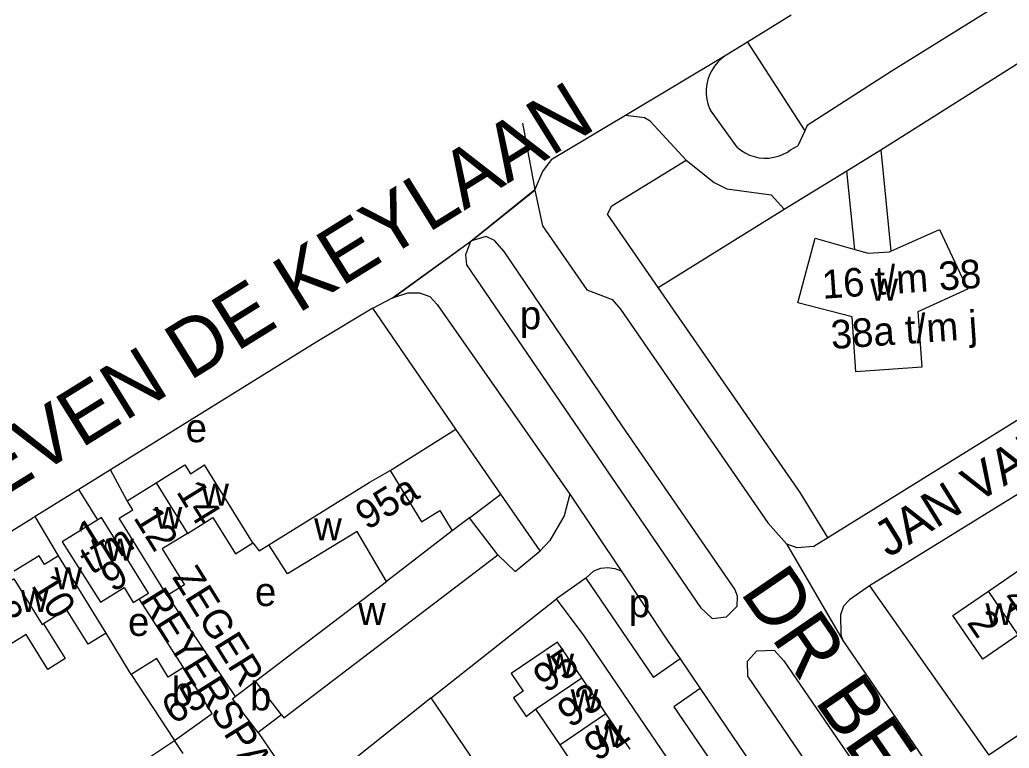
# Model space of a CAD drawing. Extents: x 159294 to 161936, y 384538 to 386517.
# Drawn here: x 159966.9 to 160105.1, y 386032 to 386133.9 of the extents above; entities that cross this region are included whole.
import ezdxf

# ---------------------------------------------------------------- set-up
doc = ezdxf.new("R2010")
doc.units = 0
for name, color, linetype in [('BLT_Basislijn', 7, 'Continuous'), ('BLT_Bebouwing', 7, 'Continuous'), ('BLT_Centroide', 7, 'Continuous'), ('BLT_Huisnummer', 7, 'Continuous'), ('BLT_Huisnummer_ tussenligend', 7, 'Continuous'), ('BLT_Huisnummer_reeks', 7, 'Continuous'), ('BLT_Onderverdeling_panden', 7, 'Continuous'), ('BLT_Straatnaam', 7, 'Continuous'), ('BLT_Straatnaam_hoofdweg', 7, 'Continuous'), ('BLT_Straatnaam_verkleind', 7, 'Continuous'), ('BLT_Vlakafsluiter', 7, 'Continuous')]:
    doc.layers.add(name, color=color, linetype=linetype)

msp = doc.modelspace()

# ---------------------------------------------------------------- linework, layer by layer
at = {"layer": 'BLT_Basislijn'}
for p, q in [((160074.68, 386134.53), (160068.54, 386130.73)), ((160087.18, 386115.71), (160114.28, 386132.8)), ((160068.54, 386130.73), (160065.43, 386128.81)), ((160068.54, 386130.73), (160076.55, 386118.35)), ((160067.09, 386116.05), (160063.37, 386121.23)), ((160076.55, 386118.35), (160075.57, 386116.26)), ((160074.57, 386115.67), (160075.57, 386116.26)), ((160082.44, 386112.75), (160087.18, 386115.71)), ((160087.18, 386115.71), (160088.57, 386101.52)), ((160073.7, 386107.39), (160082.44, 386112.75)), ((160083.57, 386101.77), (160082.44, 386112.75)), ((160056.06, 386096.42), (160073.7, 386107.39)), ((160016.21, 386093.54), (160018.95, 386094.97)), ((160027.82, 386076.64), (160016.21, 386093.54)), ((160018.61, 386070.86), (160027.82, 386076.64)), ((160034.08, 386067.52), (160027.82, 386076.64)), ((159979.53, 386070.94), (159975.13, 386068.21)), ((159981.88, 386066.61), (159979.53, 386070.94)), ((159975.13, 386068.21), (159969, 386064.41)), ((159977.75, 386063.95), (159975.13, 386068.21)), ((160029.71, 386064.24), (160034.08, 386067.52)), ((160039.58, 386059.63), (160034.08, 386067.52)), ((159969, 386064.41), (159968.68, 386064.21)), ((159972.26, 386058.9), (159969, 386064.41)), ((159999.44, 386060.73), (160000.3, 386059.6)), ((160000.3, 386059.6), (160001.66, 386060.45)), ((160045.96, 386055.8), (160041.87, 386052.91)), ((160045.96, 386055.8), (160055.44, 386041.92)), ((160085.6, 386054.73), (160102.28, 386031.05)), ((159989.76, 386043.28), (159983.54, 386052.88)), ((159987.45, 386053.35), (159996.95, 386039.23)), ((160024.34, 386039.08), (160041.87, 386052.91)), ((160133.44, 386052.12), (160102.28, 386031.05)), ((159982.43, 386042.3), (159978.95, 386048.12)), ((160059.13, 386044.49), (160055.44, 386041.92)), ((160059.13, 386044.49), (160061.94, 386040.35)), ((160061.94, 386040.35), (160058.26, 386037.79)), ((160060.25, 385986.24), (160024.34, 386039.08)), ((160058.26, 386037.79), (160116.95, 385951.89)), ((159989.68, 386031.26), (159988.48, 386033.08))]:
    msp.add_line(p, q, dxfattribs=at)
for points in [[(160133.23, 386154.38), (160088.61, 386126.62), (160076.91, 386119.1), (160076.55, 386118.35)], [(160065.43, 386128.81), (160064.88, 386128.4), (160064.38, 386127.92), (160063.94, 386127.38), (160063.56, 386126.8), (160063.26, 386126.18), (160063.02, 386125.53), (160062.86, 386124.86), (160062.79, 386124.17), (160062.79, 386123.48), (160062.87, 386122.79), (160063.03, 386122.11), (160063.26, 386121.46), (160063.37, 386121.23)], [(160079.76, 386061.47), (160132.87, 386094.43), (160177.14, 386122.35)], [(160051.51, 386120.48), (160041.11, 386114.29), (160039.9, 386112.64), (160038.85, 386110.12)], [(160059.99, 386114.26), (160054.96, 386119.69), (160054.17, 386120.16), (160051.51, 386120.48)], [(160067.09, 386116.05), (160067.62, 386115.62), (160068.21, 386115.25), (160068.83, 386114.96), (160069.49, 386114.74), (160070.16, 386114.59), (160070.85, 386114.53), (160071.53, 386114.54), (160072.22, 386114.64), (160072.88, 386114.81), (160073.53, 386115.06), (160074.14, 386115.38), (160074.57, 386115.67)], [(160056.06, 386096.42), (160048.97, 386106.69), (160049.6, 386107.86), (160059.99, 386114.26)], [(160059.99, 386114.26), (160063.92, 386111.11), (160065.67, 386110.25), (160071.86, 386109.41), (160073.7, 386107.39)], [(160038.85, 386110.12), (160038.86, 386110.06)], [(160038.86, 386110.06), (160039.9, 386105.08), (160046.1, 386096.09), (160049.65, 386094.77), (160050.83, 386093.4), (160071.42, 386063.55), (160074.02, 386060.57)], [(160051.02, 386077.09), (160034.56, 386101.49), (160033.22, 386103.02), (160032.05, 386103.56), (160030, 386102.97)], [(160029.85, 386102.85), (160029.16, 386100.99), (160029.29, 386099.61), (160062.01, 386051.71), (160063.62, 386050.17), (160065.6, 386050.39), (160067.1, 386051.87), (160067.15, 386053.27), (160066.79, 386054.25), (160051.02, 386077.09)], [(160029.88, 386102.93), (160029.85, 386102.85)], [(160030, 386102.97), (160029.88, 386102.93)], [(160158.2, 386100.41), (160157.46, 386099.94), (160123.1, 386077.89), (160085.6, 386054.73)], [(160019.11, 386095.03), (160021.07, 386095.7), (160022.72, 386095.69), (160024.17, 386095.16), (160025.21, 386094.07), (160043.75, 386067.53)], [(160079.76, 386061.47), (160075.93, 386067.77), (160056.06, 386096.42)], [(160018.95, 386094.97), (160019.11, 386095.03)], [(160016.21, 386093.54), (160008.37, 386088.83), (159979.53, 386070.94)], [(160043.75, 386067.53), (160042.92, 386064.5), (160040.92, 386061.04), (160039.58, 386059.63)], [(159928.7, 386038.51), (159929.97, 386040.26), (159968.68, 386064.21)], [(160074.02, 386060.57), (160075.44, 386060.06), (160077.83, 386060.27), (160079.76, 386061.47)], [(160033.68, 386059.06), (160036.11, 386056.74), (160039.58, 386059.63)], [(160045.96, 386055.8), (160047.06, 386056.84), (160048.06, 386057.19), (160049.02, 386057.3), (160050.03, 386057.16), (160050.91, 386056.83)], [(160050.91, 386056.83), (160057.34, 386047.14), (160059.13, 386044.49)], [(160085.6, 386054.73), (160082.8, 386052.78), (160081.99, 386051.86), (160081.55, 386050.68), (160081.62, 386047.89), (160081.9, 386047.09)], [(160079.02, 385998.73), (160045.74, 386047.71), (160041.87, 386052.91)], [(160081.9, 386047.09), (160106.25, 386011.42), (160109.38, 386007.26)], [(160112.89, 385986.9), (160129.37, 385962.53), (160129.65, 385960.05), (160128.11, 385958.54), (160125.96, 385958.61), (160124.99, 385959.5), (160119.71, 385966.84), (160068.59, 386042.09), (160068.54, 386044.17), (160069.85, 386045.65), (160072.26, 386045.73), (160073.62, 386044.23), (160112.89, 385986.9)], [(160061.94, 386040.35), (160117.48, 385958.48), (160118.52, 385956.71)], [(160024.34, 386039.08), (160007.29, 386025.46), (160007.1, 386024.81), (160041.77, 385973.34)], [(159972.92, 386023.07), (159981.65, 386028.53), (159988.48, 386033.08)], [(160000.17, 386034.21), (160003.16, 386029.82), (160001.76, 386026.15), (160001.88, 386021.96), (159998.68, 386019.17)]]:
    msp.add_lwpolyline(points, dxfattribs=at)
at = {"layer": 'BLT_Bebouwing'}
for p, q in [((159981.88, 386066.61), (159985.91, 386069.12)), ((159978.3, 386064.28), (159977.75, 386063.95)), ((160029.71, 386064.24), (160027.28, 386062.4)), ((160033.68, 386059.06), (160029.71, 386064.24)), ((160027.28, 386062.4), (160018.12, 386055.32)), ((160102.21, 386053.98), (160107.19, 386057.39)), ((159999.82, 386041.41), (160018.12, 386055.32)), ((159982.43, 386042.3), (159988.48, 386033.08)), ((159996.95, 386039.23), (159999.82, 386041.41)), ((160048.78, 386036.86), (160045.39, 386041.86)), ((159996.58, 386038.94), (159996.95, 386039.23)), ((160000, 386034.44), (159996.58, 386038.94)), ((160038.91, 386037.46), (160042.31, 386032.47)), ((160003.43, 386036.68), (160000.17, 386034.21)), ((160052.18, 386031.87), (160048.78, 386036.86)), ((160000.17, 386034.21), (160000, 386034.44)), ((160042.31, 386032.47), (160045.7, 386027.47))]:
    msp.add_line(p, q, dxfattribs=at)
for points in [[(160088.57, 386101.52), (160095.38, 386104.54), (160099.32, 386096.2), (160092.35, 386093.04), (160092.9, 386085.28), (160083.71, 386084.64), (160083.17, 386092.32), (160075.6, 386094.31), (160077.99, 386103.35), (160083.57, 386101.77)], [(160083.57, 386101.77), (160085.43, 386101.25), (160088.41, 386101.44), (160088.57, 386101.52)], [(159985.91, 386069.12), (159989.93, 386071.63), (159990.7, 386070.4), (159992.68, 386071.63)], [(159999.44, 386060.73), (159992.68, 386071.63)], [(160001.66, 386060.45), (160015.69, 386069.17), (160018.61, 386070.86)], [(160018.61, 386070.86), (160022.98, 386063.69), (160025.54, 386065.25), (160027.28, 386062.4)], [(159980.73, 386064.18), (159982.65, 386065.37), (159981.88, 386066.61)], [(159977.75, 386063.95), (159972.78, 386060.87), (159978.12, 386052.42), (159981.44, 386054.48), (159982.73, 386052.38), (159983.54, 386052.88)], [(159983.54, 386052.88), (159984.86, 386053.7), (159978.3, 386064.28)], [(159987.45, 386053.35), (159980.73, 386064.18)], [(159990.3, 386062.06), (159993.84, 386064.26), (159997.03, 386059.21), (159999.44, 386060.73)], [(159990.3, 386062.06), (159986.78, 386059.88), (159989.87, 386054.84), (159987.45, 386053.35)], [(160018.12, 386055.32), (160013.99, 386062.33), (160004.26, 386056.42), (160001.66, 386060.45)], [(159972.26, 386058.9), (159970.33, 386057.7), (159969.56, 386058.93), (159966.1, 386056.77)], [(159978.95, 386048.12), (159972.26, 386058.9)], [(160003.43, 386036.68), (160003.76, 386036.25), (160033.68, 386059.06)], [(160106.4, 386047.85), (160101.42, 386044.45), (160097.23, 386050.57), (160102.21, 386053.98)], [(159978.95, 386048.12), (159976.42, 386046.55), (159973.38, 386051.41), (159970.19, 386049.42)], [(159970.19, 386049.42), (159973.22, 386044.55), (159970.78, 386043.03), (159967.75, 386047.91), (159965.06, 386046.23)], [(160045.39, 386041.86), (160041.99, 386046.86), (160035.52, 386042.46), (160037.21, 386039.97), (160035.87, 386039.06), (160037.64, 386036.45), (160038.91, 386037.46)], [(159989.76, 386043.28), (159987.62, 386041.96), (159986, 386044.54), (159982.43, 386042.3)], [(159988.48, 386033.08), (159993.74, 386036.88), (159989.76, 386043.28)]]:
    msp.add_lwpolyline(points, dxfattribs=at)
at = {"layer": 'BLT_Onderverdeling_panden'}
for p, q in [((159985.91, 386069.12), (159990.3, 386062.06)), ((160106.4, 386047.85), (160102.21, 386053.98)), ((160003.43, 386036.68), (159999.82, 386041.41)), ((160038.91, 386037.46), (160045.39, 386041.86)), ((160042.31, 386032.47), (160048.78, 386036.86))]:
    msp.add_line(p, q, dxfattribs=at)
msp.add_lwpolyline([(159965.81, 386055.55), (159966.02, 386055.68), (159969.99, 386049.3), (159970.19, 386049.42)], dxfattribs=at)
at = {"layer": 'BLT_Vlakafsluiter'}
for p, q in [((160065.43, 386128.81), (160051.51, 386120.48)), ((160037.12, 386119.4), (160038.85, 386110.12)), ((160029.88, 386102.93), (160038.85, 386110.12)), ((160030, 386102.97), (160038.86, 386110.06)), ((160018.95, 386094.97), (160029.88, 386102.93)), ((160019.11, 386095.03), (160029.85, 386102.85)), ((160043.75, 386067.53), (160050.91, 386056.83)), ((160074.02, 386060.57), (160081.9, 386047.09))]:
    msp.add_line(p, q, dxfattribs=at)

# ---------------------------------------------------------------- texts
at = {"layer": 'BLT_Centroide'}
for s, p in [('w', (160085.72, 386094.59)), ('p', (160036.75, 386090.6)), ('e', (159990.05, 386074.8)), ('w', (159992.23, 386065.94)), ('w', (159985.72, 386062.69)), ('w', (160008, 386061.08)), ('w', (159978.95, 386058.22)), ('w', (159971.7, 386054.25)), ('w', (159967, 386051.06)), ('e', (159999.73, 386051.9)), ('w', (160014.15, 386049.25)), ('p', (160051.98, 386050.33)), ('w', (160101.81, 386049.22)), ('e', (159981.99, 386047.71)), ('w', (160040.45, 386042.16)), ('b', (159988.08, 386037.97)), ('b', (159999.03, 386037.31)), ('w', (160043.84, 386037.16)), ('w', (160047.24, 386032.16))]:
    msp.add_text(s, height=4, dxfattribs=at).set_placement(p)
at = {"layer": 'BLT_Huisnummer'}
for s, rotation, p in [('14', 301.8526, (159988.64, 386067.9)), ('95a', 31.8633, (160015.4, 386062.43)), ('12', 301.8523, (159982.66, 386064.27)), ('10', 302.0989, (159968.37, 386054.77)), ('2', 304.373, (160099.12, 386049.58)), ('95', 34.1876, (160040.4, 386039.63)), ('65', 32.1336, (159988.37, 386035.24))]:
    msp.add_text(s, height=4, rotation=rotation, dxfattribs=at).set_placement(p)
at = {"layer": 'BLT_Huisnummer_ tussenligend'}
for s, rotation, p in [('8', 301.7708, (159962.67, 386051.14)), ('4', 304.373, (160103.96, 386052.86)), ('93', 34.1876, (160043.77, 386034.75)), ('91', 34.1876, (160047.51, 386030.07))]:
    msp.add_text(s, height=4, rotation=rotation, dxfattribs=at).set_placement(p)
at = {"layer": 'BLT_Huisnummer_reeks'}
for s, rotation, p in [('16 t/m 38', 4.0346, (160079.08, 386094.85)), ('38a t/m j', 4.0346, (160080.33, 386087.82)), ('1', 31.9097, (159976.52, 386059.51)), ('t/m', 31.9097, (159976.89, 386056.19)), ('9', 31.9097, (159979.85, 386053.73))]:
    msp.add_text(s, height=4, rotation=rotation, dxfattribs=at).set_placement(p)
at = {"layer": 'BLT_Straatnaam'}
for s, rotation, p in [('JAN VAN DEN EYNDESTRAAT', 31.7179, (160088.23, 386058.59)), ('HENDRIK DE KEYZERPLEIN', 301.9791, (159920.07, 386032.72))]:
    msp.add_text(s, height=5, rotation=rotation, dxfattribs=at).set_placement(p)
at = {"layer": 'BLT_Straatnaam_hoofdweg'}
for s, rotation, p in [('1E LIEVEN DE KEYLAAN', 31.8658, (159942.1, 386053.16)), ('DR BERLAGELAAN', 304.4066, (160067.41, 386053.82))]:
    msp.add_text(s, height=8, rotation=rotation, dxfattribs=at).set_placement(p)
at = {"layer": 'BLT_Straatnaam_verkleind'}
for s, p in [('ZEGER ', (159988.08, 386055.93)), ('REYERSPAD', (159983.6, 386052.78))]:
    msp.add_text(s, height=4, rotation=301.9611, dxfattribs=at).set_placement(p)

doc.saveas('drawing.dxf')
